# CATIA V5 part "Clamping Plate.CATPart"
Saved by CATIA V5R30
Part number: Holding Plate
Bounding box of the stored display mesh (mm): x -16 to 16, y -16 to 16, z 0 to 7
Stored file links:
  D:\PROJECTS\Resources\c13\c13tut2\Bench vice\Clamping Plate.CATPart
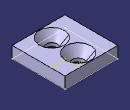
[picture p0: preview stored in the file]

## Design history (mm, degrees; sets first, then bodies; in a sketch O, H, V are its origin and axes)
Body1 (main body)
  Sketch1 on xy-plane, origin (0, 0, 0), H (1, 0, 0), V (0, 1, 0)
    line L1 (-16, 16) -> (16, 16)
    line L2 (16, 16) -> (16, -16)
    line L3 (16, -16) -> (-16, -16)
    line L4 (-16, -16) -> (-16, 16)
    construction line L5 (-16, 16) -> (16, -16)
    length L2 = 32
    length L3 = 32
    distance H L3 = 16
    distance V L4 = 16
    horizontal: L1 H, L3 H
    vertical: L2 V, L4 V
  Pad1: profile Sketch1, direction (0, 0, 1), length 7
  Sketch2 on face of Pad1, origin (-0.9262, 8.6399, 7), H (1, 0, 0), V (0, 1, 0)
    point P1 (0.9262, -0.6399)
    reference intersected line E1 through (0.9262, 0) direction (0, 1) from yz-plane
    reference projected line E3 (-15.0738, 7.3601) -> (16.9262, 7.3601) from edge of Pad1
    distance P1 E3 = 8
    coincidence: E1 P1
  Hole1: placed by Sketch2, at (0, 8, 7) direction (0, 0, -1), diameter 7, depth 10, countersink depth 5, countersink angle 80
  Mirror1: of Hole1, about zx-plane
